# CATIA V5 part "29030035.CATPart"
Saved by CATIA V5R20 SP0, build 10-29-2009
Part number: 29030035
Definition: NONE
Nomenclature: 29030035
Source: Unknown
Description: 29030035
Bounding box of the stored display mesh (mm): x -17.5 to 44.548, y -29 to 63.548, z -19 to 19
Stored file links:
  C:\Users\Utente\Desktop\IO LAVORO\3D X SITO CF\X SITO\PLASTICA\RF1\29030035.CATPart
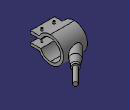
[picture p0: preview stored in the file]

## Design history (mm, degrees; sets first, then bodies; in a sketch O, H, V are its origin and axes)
Body1 "29030035" (main body)
  Solid1: solid without history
